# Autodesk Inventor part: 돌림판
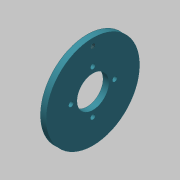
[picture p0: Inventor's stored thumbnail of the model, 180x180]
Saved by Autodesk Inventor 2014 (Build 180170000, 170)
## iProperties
Created: 2019-10
Part Number: 돌림판
Material: 스테인리스강
Document SubType Name: Modeling
Designer: mduedu
Density: 1 g/cm^3
Appearance: 커뎃 파란색
Author: mduedu
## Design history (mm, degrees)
sketch "스케치1" dims "d3" = 30
  geometry: C1 r 32 at (0, 0); C2 r 11 at (0, 0); C3 r 1.7 at (15, 0); C4 r 1.7 at (0, 15); C5 r 1.7 at (-15, 0); C6 r 1.7 at (0, -15); 2 further points
  constraints: 6 centre point, 3 coincident, 2 horizontal alignment, 11 other
  dimensions: "d0" = 64 diameter of C1; "d2" = 3.4 diameter of C3; "d4" = 22 diameter of C2; "d7" = 360 deg dimension on point (0, 0) C3.centre (derived)
extrude "돌출1" new body sketch "스케치1" distance "d9" = 4; taper "d10" = 0 deg
sketch "스케치2" dims "d11" = 54
  geometry: 3 further points
  constraints: 2 vertical alignment, 1 coincident, 2 other
hole "구멍1" sketch "스케치2" at (0, 27) diameter "d13" = 3.242; stored, may be unused: countersink angle "d17" = 90 deg, drill point angle "d19" = 118 deg; dims "d14" = 6, "d15" = 4, "d16" = 2, "d18" = 8
node "솔리드1"
